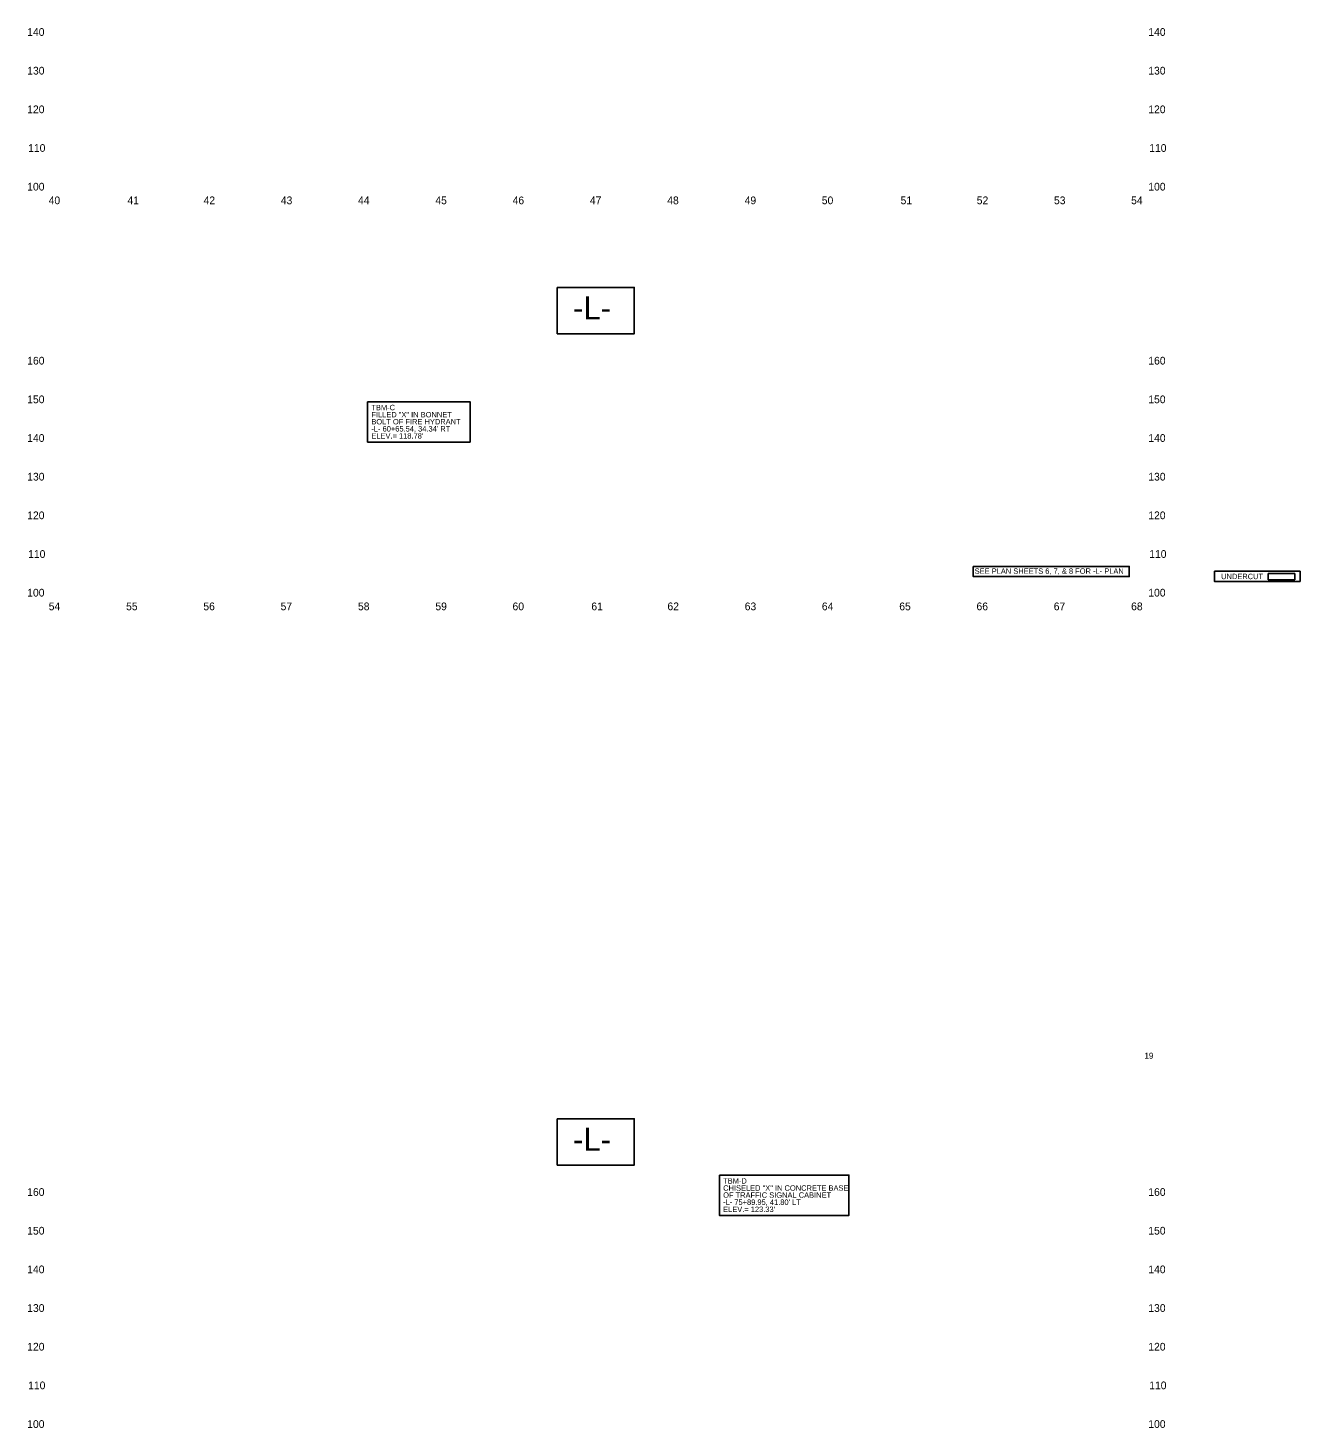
# Model space of a CAD drawing. Extents: x 2364289 to 2366249, y 588759 to 610062.
# Drawn here: x 2364469 to 2366114, y 606377 to 608187 of the extents above; entities that cross this region are included whole.
import ezdxf

# ---------------------------------------------------------------- set-up
doc = ezdxf.new("R2010")
doc.units = 0
for name, color, linetype in [('Exist Vertical Profile Horizontal Axis Label Major', 7, 'Continuous'), ('Exist Vertical Profile Vertical Axis Label', 7, 'Continuous'), ('Prop CMT Shallow Undercut', 7, 'Continuous'), ('Prop DSN Text', 7, 'Continuous'), ('Prop Grid Mask', 7, 'Continuous'), ('Sheet Data Field CELL', 7, 'Continuous')]:
    doc.layers.add(name, color=color, linetype=linetype)

msp = doc.modelspace()

# ---------------------------------------------------------------- linework, layer by layer
at = {"layer": 'Prop CMT Shallow Undercut'}
msp.add_lwpolyline([(2366073.2, 607481.3), (2366107.5, 607481.3), (2366107.5, 607473.4), (2366073.2, 607473.4)], close=True, dxfattribs=at)
msp.add_lwpolyline([(2366073.2, 607473.4), (2366107.5, 607473.4), (2366107.5, 607481.3), (2366073.2, 607481.3), (2366073.2, 607473.4)], dxfattribs=at)
at = {"layer": 'Prop Grid Mask'}
for points in [[(2365153.5, 607851.5), (2365253.2, 607851.5), (2365253.2, 607791.6), (2365153.5, 607791.6)], [(2364908.3, 607703.7), (2365040.7, 607703.7), (2365040.7, 607651.5), (2364908.3, 607651.5)], [(2365691.6, 607490.7), (2365893.3, 607490.7), (2365893.3, 607477.5), (2365691.6, 607477.5)], [(2366003.5, 607484.4), (2366114.2, 607484.4), (2366114.2, 607471.2), (2366003.5, 607471.2)], [(2365153.5, 606776.5), (2365253.2, 606776.5), (2365253.2, 606716.6), (2365153.5, 606716.6)], [(2365363.3, 606703.7), (2365530.7, 606703.7), (2365530.7, 606651.5), (2365363.3, 606651.5)]]:
    msp.add_lwpolyline(points, close=True, dxfattribs=at)

# ---------------------------------------------------------------- texts
at = {"layer": 'Exist Vertical Profile Horizontal Axis Label Major'}
for s, p in [('40', (2364495.7, 607959)), ('41', (2364597.6, 607959)), ('42', (2364696.1, 607959)), ('43', (2364796, 607959)), ('44', (2364895.8, 607959)), ('45', (2364995.9, 607959)), ('46', (2365095.8, 607959)), ('47', (2365195.7, 607959)), ('48', (2365295.8, 607959)), ('49', (2365395.9, 607959)), ('50', (2365495.7, 607959)), ('51', (2365597.6, 607959)), ('52', (2365696.1, 607959)), ('53', (2365796, 607959)), ('54', (2365895.8, 607959)), ('54', (2364495.8, 607434)), ('55', (2364595.9, 607434)), ('56', (2364695.8, 607434)), ('57', (2364795.7, 607434)), ('58', (2364895.8, 607434)), ('59', (2364995.9, 607434)), ('60', (2365095.7, 607434)), ('61', (2365197.6, 607434)), ('62', (2365296.1, 607434)), ('63', (2365396, 607434)), ('64', (2365495.8, 607434)), ('65', (2365595.9, 607434)), ('66', (2365695.8, 607434)), ('67', (2365795.7, 607434)), ('68', (2365895.8, 607434))]:
    msp.add_text(s, height=10, dxfattribs=at).set_placement(p)
at = {"layer": 'Exist Vertical Profile Vertical Axis Label'}
for s, p in [('140', (2364468, 608176.7)), ('140', (2364468, 608176.7)), ('140', (2365918, 608176.7)), ('130', (2364468, 608126.7)), ('130', (2364468, 608126.7)), ('130', (2365918, 608126.7)), ('120', (2364468, 608076.7)), ('120', (2364468, 608076.7)), ('120', (2365918, 608076.7)), ('110', (2364469.2, 608026.7)), ('110', (2364469.2, 608026.7)), ('110', (2365919.2, 608026.7)), ('100', (2364468, 607976.7)), ('100', (2364468, 607976.7)), ('100', (2365918, 607976.7)), ('160', (2364468, 607751.7)), ('160', (2364468, 607751.7)), ('160', (2365918, 607751.7)), ('150', (2364468, 607701.7)), ('150', (2364468, 607701.7)), ('150', (2365918, 607701.7)), ('140', (2364468, 607651.7)), ('140', (2364468, 607651.7)), ('140', (2365918, 607651.7)), ('130', (2364468, 607601.7)), ('130', (2364468, 607601.7)), ('130', (2365918, 607601.7)), ('120', (2364468, 607551.7)), ('120', (2364468, 607551.7)), ('120', (2365918, 607551.7)), ('110', (2364469.2, 607501.7)), ('110', (2364469.2, 607501.7)), ('110', (2365919.2, 607501.7)), ('100', (2364468, 607451.7)), ('100', (2364468, 607451.7)), ('100', (2365918, 607451.7)), ('160', (2364468, 606676.7)), ('160', (2365918, 606676.7)), ('150', (2364468, 606626.7)), ('150', (2365918, 606626.7)), ('140', (2364468, 606576.7)), ('140', (2365918, 606576.7)), ('130', (2364468, 606526.7)), ('130', (2365918, 606526.7)), ('120', (2364468, 606476.7)), ('120', (2365918, 606476.7)), ('110', (2364469.2, 606426.7)), ('110', (2365919.2, 606426.7)), ('100', (2364468, 606376.7)), ('100', (2365918, 606376.7))]:
    msp.add_text(s, height=10, dxfattribs=at).set_placement(p)
at = {"layer": 'Prop DSN Text'}
for s, p in [('TBM-C', (2364913.1, 607692.6)), ('FILLED "X" IN BONNET ', (2364913.1, 607683.4)), ('BOLT OF FIRE HYDRANT', (2364913.1, 607674.3)), ("-L- 60+65.54, 34.34' RT", (2364913.1, 607665.1)), ("ELEV.= 118.78'", (2364913.1, 607655.9)), ('SEE PLAN SHEETS 6, 7, & 8 FOR -L- PLAN', (2365693.4, 607481.1)), ('UNDERCUT', (2366012.2, 607474.2)), ('TBM-D', (2365368.1, 606692.6)), ('CHISELED "X" IN CONCRETE BASE ', (2365368.1, 606683.4)), ("-L- 75+89.95, 41.80' LT", (2365368.1, 606665.1)), ('OF TRAFFIC SIGNAL CABINET', (2365368.1, 606674.3)), ("ELEV.= 123.33'", (2365368.1, 606655.9))]:
    msp.add_text(s, height=7, dxfattribs=at).set_placement(p)
at = {"layer": 'Prop Grid Mask'}
for p in [(2365174, 607810), (2365174, 606735)]:
    msp.add_text('-L-', height=30, dxfattribs=at).set_placement(p)
at = {"layer": 'Sheet Data Field CELL'}
msp.add_text('19', height=7.75, dxfattribs=at).set_placement((2365913, 606854.1))

doc.saveas('drawing.dxf')
